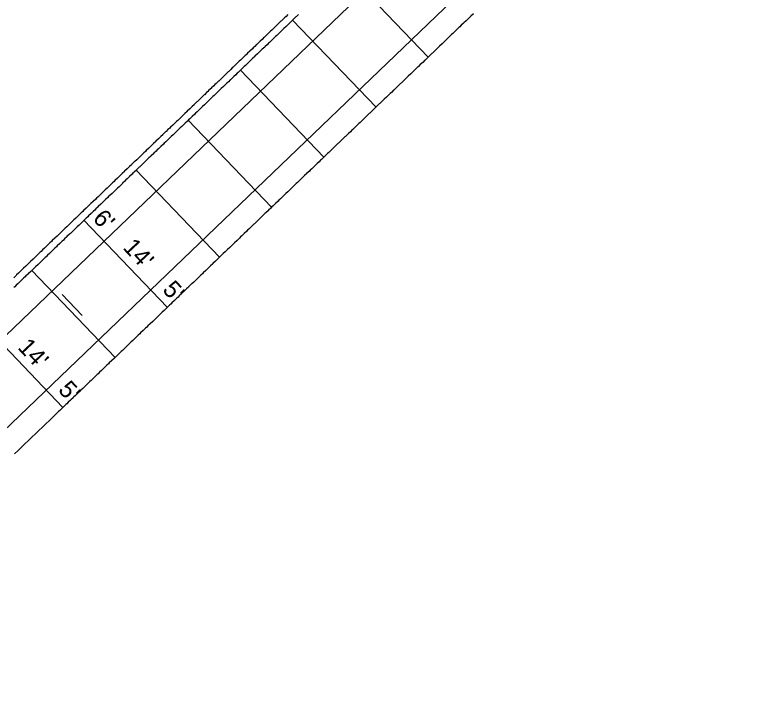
# Model space of a CAD drawing. Extents: x 2145147 to 2158018, y 137519 to 148068.
# Drawn here: x 2150146.3 to 2150298.8, y 143521.5 to 143665.3 of the extents above; entities that cross this region are included whole.
import ezdxf

# ---------------------------------------------------------------- set-up
doc = ezdxf.new("R2010")
doc.units = 0
for name, color, linetype in [('PR_Align_Ramp_B', 7, 'Continuous'), ('PR_Align_Ramp_F', 7, 'Continuous'), ('PR_Dimensions', 7, 'Continuous'), ('PR_Joint_Contraction', 7, 'Continuous'), ('PR_Joint_Long', 7, 'Continuous'), ('PR_Road_Concrete', 7, 'Continuous')]:
    doc.layers.add(name, color=color, linetype=linetype)

msp = doc.modelspace()

# ---------------------------------------------------------------- linework, layer by layer
at = {"layer": 'PR_Align_Ramp_B'}
msp.add_arc((2151085.75, 143191.05), 848.83, 152.5051, 261.84091, dxfattribs=at)
at = {"layer": 'PR_Align_Ramp_F'}
msp.add_lwpolyline([(2150160.31, 143602.96), (2150156.16, 143607.29)], dxfattribs=at)
at = {"layer": 'PR_Joint_Contraction'}
for p, q in [((2150232.12, 143656.54), (2150214.82, 143674.59)), ((2150221.29, 143646.17), (2150203.99, 143664.22)), ((2150210.46, 143635.79), (2150193.16, 143653.84)), ((2150199.63, 143625.41), (2150182.33, 143643.46)), ((2150188.8, 143615.03), (2150171.5, 143633.08)), ((2150177.97, 143604.65), (2150160.67, 143622.7)), ((2150167.14, 143594.27), (2150149.84, 143612.32)), ((2150156.31, 143583.9), (2150139.01, 143601.94))]:
    msp.add_line(p, q, dxfattribs=at)
at = {"layer": 'PR_Joint_Long'}
for points in [[(2150341.04, 143787.25), (2149920.61, 143384.33)], [(2150350.73, 143777.14), (2149930.29, 143374.23)]]:
    msp.add_lwpolyline(points, dxfattribs=at)
at = {"layer": 'PR_Road_Concrete'}
for points in [[(2150203.01, 143665.36), (2150202.64, 143665), (2150202.29, 143664.66), (2150202.14, 143664.52), (2150201.64, 143664.05), (2150201.56, 143663.97), (2150201.14, 143663.57), (2150200.84, 143663.28), (2150200.64, 143663.09), (2150200.14, 143662.61), (2150200.12, 143662.59), (2150199.64, 143662.13), (2150199.4, 143661.9), (2150199.14, 143661.65), (2150198.68, 143661.2), (2150198.64, 143661.17), (2150198.14, 143660.69), (2150197.95, 143660.51), (2150197.63, 143660.21), (2150197.23, 143659.82), (2150197.13, 143659.73), (2150196.63, 143659.25), (2150196.51, 143659.13), (2150196.13, 143658.77), (2150195.79, 143658.44), (2150195.63, 143658.29), (2150195.13, 143657.81), (2150195.07, 143657.75), (2150194.63, 143657.33), (2150194.34, 143657.05), (2150194.13, 143656.85), (2150193.63, 143656.37), (2150193.62, 143656.36), (2150193.13, 143655.89), (2150192.9, 143655.67), (2150192.63, 143655.41), (2150192.18, 143654.98), (2150192.13, 143654.93), (2150191.63, 143654.45), (2150191.46, 143654.29), (2150191.13, 143653.97), (2150190.73, 143653.59), (2150190.63, 143653.49), (2150190.13, 143653.01), (2150190.01, 143652.9), (2150189.63, 143652.53), (2150189.29, 143652.21), (2150189.13, 143652.05), (2150188.63, 143651.57), (2150188.57, 143651.52), (2150188.13, 143651.09), (2150187.85, 143650.83), (2150187.62, 143650.61), (2150187.12, 143650.14), (2150187.12, 143650.13), (2150186.62, 143649.66), (2150186.4, 143649.44), (2150186.12, 143649.18), (2150185.68, 143648.75), (2150185.62, 143648.7), (2150185.12, 143648.22), (2150184.96, 143648.06), (2150184.62, 143647.74), (2150184.24, 143647.37), (2150184.12, 143647.26), (2150183.62, 143646.78), (2150183.51, 143646.67), (2150183.12, 143646.3), (2150182.79, 143645.98), (2150182.62, 143645.82), (2150182.12, 143645.34), (2150182.07, 143645.29), (2150181.62, 143644.86), (2150181.35, 143644.6), (2150181.12, 143644.38), (2150180.63, 143643.91), (2150180.62, 143643.9), (2150180.12, 143643.42), (2150179.9, 143643.22), (2150179.62, 143642.94), (2150179.18, 143642.52), (2150179.12, 143642.46), (2150178.62, 143641.98), (2150178.46, 143641.83), (2150178.11, 143641.5), (2150177.74, 143641.14), (2150177.61, 143641.02), (2150177.11, 143640.54), (2150177.02, 143640.45), (2150176.61, 143640.06), (2150176.29, 143639.76), (2150176.11, 143639.58), (2150175.61, 143639.1), (2150175.57, 143639.06), (2150175.11, 143638.62), (2150174.85, 143638.37), (2150174.61, 143638.14), (2150174.13, 143637.68), (2150174.11, 143637.66), (2150173.61, 143637.18), (2150173.41, 143636.99), (2150173.11, 143636.7), (2150172.68, 143636.3), (2150172.61, 143636.23), (2150172.11, 143635.75), (2150171.96, 143635.6), (2150171.61, 143635.27), (2150171.24, 143634.91), (2150171.11, 143634.79), (2150170.61, 143634.31), (2150170.52, 143634.22), (2150170.11, 143633.83), (2150169.8, 143633.53), (2150169.61, 143633.35), (2150169.11, 143632.87), (2150169.07, 143632.84), (2150168.61, 143632.39), (2150168.35, 143632.14), (2150168.1, 143631.91), (2150167.63, 143631.45), (2150167.6, 143631.43), (2150167.1, 143630.95), (2150166.91, 143630.76), (2150166.6, 143630.47), (2150166.19, 143630.07), (2150166.1, 143629.99), (2150165.6, 143629.51), (2150165.46, 143629.38), (2150165.1, 143629.03), (2150164.74, 143628.69), (2150164.6, 143628.55), (2150164.1, 143628.07), (2150164.02, 143627.99), (2150163.6, 143627.59), (2150163.3, 143627.3), (2150163.1, 143627.11), (2150162.6, 143626.63), (2150162.58, 143626.61), (2150162.1, 143626.15), (2150161.85, 143625.92), (2150161.6, 143625.67), (2150161.13, 143625.23), (2150161.1, 143625.19), (2150160.6, 143624.71), (2150160.41, 143624.53), (2150160.1, 143624.23), (2150159.69, 143623.84), (2150159.6, 143623.75), (2150159.1, 143623.27), (2150158.97, 143623.15), (2150158.59, 143622.79), (2150158.24, 143622.46), (2150158.09, 143622.32), (2150157.59, 143621.84), (2150157.52, 143621.77), (2150157.09, 143621.36), (2150156.8, 143621.07), (2150156.59, 143620.88), (2150156.09, 143620.4), (2150156.08, 143620.38), (2150155.59, 143619.92), (2150155.36, 143619.69), (2150155.09, 143619.44), (2150154.63, 143619), (2150154.59, 143618.96), (2150154.09, 143618.48), (2150153.91, 143618.31), (2150153.59, 143618), (2150153.19, 143617.61), (2150153.09, 143617.52), (2150152.59, 143617.04), (2150152.47, 143616.92), (2150152.09, 143616.56), (2150151.75, 143616.23), (2150151.59, 143616.08), (2150151.09, 143615.6), (2150151.02, 143615.54), (2150150.59, 143615.12), (2150150.3, 143614.85), (2150150.09, 143614.64), (2150149.59, 143614.16), (2150149.58, 143614.16), (2150149.09, 143613.68), (2150148.86, 143613.46), (2150148.58, 143613.2), (2150148.14, 143612.77), (2150148.08, 143612.72), (2150147.58, 143612.24), (2150147.41, 143612.08), (2150147.08, 143611.76), (2150146.69, 143611.39), (2150146.58, 143611.28), (2150146.08, 143610.8)], [(2150205.18, 143665.36), (2150204.77, 143664.96), (2150204.68, 143664.88), (2150204.18, 143664.4), (2150204.05, 143664.27), (2150203.68, 143663.92), (2150203.33, 143663.58), (2150203.18, 143663.44), (2150202.68, 143662.96), (2150202.61, 143662.88), (2150202.18, 143662.48), (2150201.88, 143662.19), (2150201.68, 143662), (2150201.18, 143661.52), (2150201.16, 143661.5), (2150200.68, 143661.04), (2150200.44, 143660.81), (2150200.18, 143660.56), (2150199.72, 143660.12), (2150199.68, 143660.08), (2150199.18, 143659.6), (2150199, 143659.43), (2150198.68, 143659.12), (2150198.27, 143658.73), (2150198.18, 143658.64), (2150197.68, 143658.16), (2150197.55, 143658.04), (2150197.18, 143657.68), (2150196.83, 143657.35), (2150196.68, 143657.2), (2150196.17, 143656.72), (2150196.11, 143656.66), (2150195.67, 143656.24), (2150195.39, 143655.97), (2150195.17, 143655.76), (2150194.67, 143655.28), (2150194.66, 143655.27), (2150194.17, 143654.8), (2150193.94, 143654.58), (2150193.67, 143654.32), (2150193.22, 143653.89), (2150193.17, 143653.84), (2150192.67, 143653.36), (2150192.5, 143653.2), (2150192.17, 143652.88), (2150191.78, 143652.51), (2150191.67, 143652.4), (2150191.17, 143651.93), (2150191.05, 143651.81), (2150190.67, 143651.45), (2150190.33, 143651.12), (2150190.17, 143650.97), (2150189.67, 143650.49), (2150189.61, 143650.43), (2150189.17, 143650.01), (2150188.89, 143649.74), (2150188.67, 143649.53), (2150188.17, 143649.05), (2150188.17, 143649.05), (2150187.67, 143648.57), (2150187.44, 143648.35), (2150187.17, 143648.09), (2150186.72, 143647.66), (2150186.67, 143647.61), (2150186.16, 143647.13), (2150186, 143646.97), (2150185.66, 143646.65), (2150185.28, 143646.28), (2150185.16, 143646.17), (2150184.66, 143645.69), (2150184.56, 143645.59), (2150184.16, 143645.21), (2150183.83, 143644.9), (2150183.66, 143644.73), (2150183.16, 143644.25), (2150183.11, 143644.2), (2150182.66, 143643.77), (2150182.39, 143643.51), (2150182.16, 143643.29), (2150181.67, 143642.82), (2150181.66, 143642.81), (2150181.16, 143642.33), (2150180.95, 143642.13), (2150180.66, 143641.85), (2150180.22, 143641.44), (2150180.16, 143641.37), (2150179.66, 143640.89), (2150179.5, 143640.74), (2150179.16, 143640.41), (2150178.78, 143640.05), (2150178.66, 143639.93), (2150178.16, 143639.45), (2150178.06, 143639.36), (2150177.66, 143638.97), (2150177.34, 143638.67), (2150177.16, 143638.49), (2150176.65, 143638.02), (2150176.61, 143637.98), (2150176.15, 143637.54), (2150175.89, 143637.28), (2150175.65, 143637.06), (2150175.17, 143636.59), (2150175.15, 143636.58), (2150174.65, 143636.1), (2150174.45, 143635.9), (2150174.15, 143635.62), (2150173.73, 143635.21), (2150173.65, 143635.14), (2150173.15, 143634.66), (2150173, 143634.52), (2150172.65, 143634.18), (2150172.28, 143633.82), (2150172.15, 143633.7), (2150171.65, 143633.22), (2150171.56, 143633.13), (2150171.15, 143632.74), (2150170.84, 143632.44), (2150170.65, 143632.26), (2150170.15, 143631.78), (2150170.12, 143631.75), (2150169.65, 143631.3), (2150169.39, 143631.06), (2150169.15, 143630.82), (2150168.67, 143630.37), (2150168.65, 143630.34), (2150168.15, 143629.86), (2150167.95, 143629.67), (2150167.65, 143629.38), (2150167.23, 143628.98), (2150167.15, 143628.9), (2150166.64, 143628.42), (2150166.51, 143628.29), (2150166.14, 143627.94), (2150165.78, 143627.6), (2150165.64, 143627.46), (2150165.14, 143626.98), (2150165.06, 143626.91), (2150164.64, 143626.5), (2150164.34, 143626.21), (2150164.14, 143626.02), (2150163.64, 143625.54), (2150163.62, 143625.52), (2150163.14, 143625.06), (2150162.9, 143624.83), (2150162.64, 143624.58), (2150162.17, 143624.14), (2150162.14, 143624.11), (2150161.64, 143623.63), (2150161.45, 143623.45), (2150161.14, 143623.15), (2150160.73, 143622.75), (2150160.64, 143622.67), (2150160.14, 143622.19), (2150160.01, 143622.06), (2150159.64, 143621.71), (2150159.29, 143621.37), (2150159.14, 143621.23), (2150158.64, 143620.75), (2150158.56, 143620.68), (2150158.14, 143620.27), (2150157.84, 143619.99), (2150157.64, 143619.79), (2150157.13, 143619.31), (2150157.12, 143619.29), (2150156.63, 143618.83), (2150156.4, 143618.6), (2150156.13, 143618.35), (2150155.68, 143617.91), (2150155.63, 143617.87), (2150155.13, 143617.39), (2150154.95, 143617.22), (2150154.63, 143616.91), (2150154.23, 143616.53), (2150154.13, 143616.43), (2150153.63, 143615.95), (2150153.51, 143615.84), (2150153.13, 143615.47), (2150152.79, 143615.14), (2150152.63, 143614.99), (2150152.13, 143614.51), (2150152.07, 143614.45), (2150151.63, 143614.03), (2150151.34, 143613.76), (2150151.13, 143613.55), (2150150.63, 143613.07), (2150150.62, 143613.07), (2150150.13, 143612.59), (2150149.9, 143612.38), (2150149.63, 143612.11), (2150149.18, 143611.68), (2150149.13, 143611.63), (2150148.63, 143611.15), (2150148.46, 143610.99), (2150148.13, 143610.67), (2150147.73, 143610.3), (2150147.63, 143610.2), (2150147.12, 143609.72), (2150147.01, 143609.61), (2150146.62, 143609.24), (2150146.29, 143608.92), (2150146.12, 143608.76)], [(2150241.5, 143665.54), (2150241, 143665.06), (2150240.84, 143664.9), (2150240.5, 143664.58), (2150240.12, 143664.21), (2150240, 143664.1), (2150239.5, 143663.62), (2150239.39, 143663.52), (2150239, 143663.14), (2150238.67, 143662.83), (2150238.5, 143662.66), (2150238, 143662.18), (2150237.95, 143662.13), (2150237.49, 143661.7), (2150237.23, 143661.44), (2150236.99, 143661.22), (2150236.51, 143660.75), (2150236.49, 143660.74), (2150235.99, 143660.26), (2150235.78, 143660.06), (2150235.49, 143659.78), (2150235.06, 143659.37), (2150234.99, 143659.3), (2150234.49, 143658.82), (2150234.34, 143658.68), (2150233.99, 143658.34), (2150233.62, 143657.98), (2150233.49, 143657.86), (2150232.99, 143657.38), (2150232.9, 143657.29), (2150232.49, 143656.9), (2150232.17, 143656.6), (2150231.99, 143656.42), (2150231.49, 143655.94), (2150231.45, 143655.91), (2150230.99, 143655.46), (2150230.73, 143655.22), (2150230.49, 143654.98), (2150230.01, 143654.52), (2150229.99, 143654.5), (2150229.49, 143654.02), (2150229.29, 143653.83), (2150228.99, 143653.54), (2150228.56, 143653.14), (2150228.49, 143653.06), (2150227.98, 143652.58), (2150227.84, 143652.45), (2150227.48, 143652.1), (2150227.12, 143651.76), (2150226.98, 143651.63), (2150226.48, 143651.15), (2150226.4, 143651.06), (2150225.98, 143650.67), (2150225.68, 143650.37), (2150225.48, 143650.19), (2150224.98, 143649.71), (2150224.95, 143649.68), (2150224.48, 143649.23), (2150224.23, 143648.99), (2150223.98, 143648.75), (2150223.51, 143648.3), (2150223.48, 143648.27), (2150222.98, 143647.79), (2150222.79, 143647.6), (2150222.48, 143647.31), (2150222.07, 143646.91), (2150221.98, 143646.83), (2150221.48, 143646.35), (2150221.34, 143646.22), (2150220.98, 143645.87), (2150220.62, 143645.53), (2150220.48, 143645.39), (2150219.98, 143644.91), (2150219.9, 143644.84), (2150219.48, 143644.43), (2150219.18, 143644.15), (2150218.98, 143643.95), (2150218.48, 143643.47), (2150218.46, 143643.45), (2150217.97, 143642.99), (2150217.73, 143642.76), (2150217.47, 143642.51), (2150217.01, 143642.07), (2150216.97, 143642.03), (2150216.47, 143641.55), (2150216.29, 143641.38), (2150215.97, 143641.07), (2150215.57, 143640.69), (2150215.47, 143640.59), (2150214.97, 143640.11), (2150214.85, 143639.99), (2150214.47, 143639.63), (2150214.12, 143639.3), (2150213.97, 143639.15), (2150213.47, 143638.67), (2150213.4, 143638.61), (2150212.97, 143638.19), (2150212.68, 143637.92), (2150212.47, 143637.72), (2150211.97, 143637.24), (2150211.96, 143637.23), (2150211.47, 143636.76), (2150211.24, 143636.53), (2150210.97, 143636.28), (2150210.52, 143635.84), (2150210.47, 143635.8), (2150209.97, 143635.32), (2150209.79, 143635.15), (2150209.47, 143634.84), (2150209.07, 143634.46), (2150208.97, 143634.36), (2150208.46, 143633.88), (2150208.35, 143633.77), (2150207.96, 143633.4), (2150207.63, 143633.07), (2150207.46, 143632.92), (2150206.96, 143632.44), (2150206.91, 143632.38), (2150206.46, 143631.96), (2150206.18, 143631.69), (2150205.96, 143631.48), (2150205.46, 143631), (2150205.46, 143631), (2150204.96, 143630.52), (2150204.74, 143630.31), (2150204.46, 143630.04), (2150204.02, 143629.62), (2150203.96, 143629.56), (2150203.46, 143629.08), (2150203.3, 143628.92), (2150202.96, 143628.6), (2150202.57, 143628.23), (2150202.46, 143628.12), (2150201.96, 143627.64), (2150201.85, 143627.54), (2150201.46, 143627.16), (2150201.13, 143626.85), (2150200.96, 143626.68), (2150200.46, 143626.2), (2150200.41, 143626.16), (2150199.96, 143625.72), (2150199.69, 143625.46), (2150199.46, 143625.24), (2150198.96, 143624.77), (2150198.96, 143624.76), (2150198.45, 143624.28), (2150198.24, 143624.08), (2150197.95, 143623.81), (2150197.52, 143623.39), (2150197.45, 143623.33), (2150196.95, 143622.85), (2150196.8, 143622.7), (2150196.45, 143622.37), (2150196.08, 143622), (2150195.95, 143621.89), (2150195.45, 143621.41), (2150195.35, 143621.31), (2150194.95, 143620.93), (2150194.63, 143620.62), (2150194.45, 143620.45), (2150193.95, 143619.97), (2150193.91, 143619.93), (2150193.45, 143619.49), (2150193.19, 143619.24), (2150192.95, 143619.01), (2150192.47, 143618.54), (2150192.45, 143618.53), (2150191.95, 143618.05), (2150191.74, 143617.85), (2150191.45, 143617.57), (2150191.02, 143617.16), (2150190.95, 143617.09), (2150190.45, 143616.61), (2150190.3, 143616.47), (2150189.95, 143616.13), (2150189.58, 143615.78), (2150189.45, 143615.65), (2150188.94, 143615.17), (2150188.86, 143615.09), (2150188.44, 143614.69), (2150188.13, 143614.39), (2150187.94, 143614.21), (2150187.44, 143613.73), (2150187.41, 143613.7), (2150186.94, 143613.25), (2150186.69, 143613.01), (2150186.44, 143612.77), (2150185.97, 143612.32), (2150185.94, 143612.29), (2150185.44, 143611.81), (2150185.25, 143611.63), (2150184.94, 143611.33), (2150184.52, 143610.93), (2150184.44, 143610.85), (2150183.94, 143610.37), (2150183.8, 143610.24), (2150183.44, 143609.9), (2150183.08, 143609.55), (2150182.94, 143609.42), (2150182.44, 143608.94), (2150182.36, 143608.86), (2150181.94, 143608.46), (2150181.64, 143608.17), (2150181.44, 143607.98), (2150180.94, 143607.5), (2150180.91, 143607.47), (2150180.44, 143607.02), (2150180.19, 143606.78), (2150179.94, 143606.54), (2150179.47, 143606.09), (2150179.44, 143606.06), (2150178.93, 143605.58), (2150178.75, 143605.4), (2150178.43, 143605.1), (2150178.03, 143604.71), (2150177.93, 143604.62), (2150177.43, 143604.14), (2150177.3, 143604.01), (2150176.93, 143603.66), (2150176.58, 143603.32), (2150176.43, 143603.18), (2150175.93, 143602.7), (2150175.86, 143602.63), (2150175.43, 143602.22), (2150175.14, 143601.94), (2150174.93, 143601.74), (2150174.43, 143601.26), (2150174.42, 143601.25), (2150173.93, 143600.78), (2150173.69, 143600.56), (2150173.43, 143600.3), (2150172.97, 143599.86), (2150172.93, 143599.82), (2150172.43, 143599.34), (2150172.25, 143599.17), (2150171.93, 143598.86), (2150171.53, 143598.48), (2150171.43, 143598.38), (2150170.93, 143597.9), (2150170.81, 143597.79), (2150170.43, 143597.42), (2150170.08, 143597.1), (2150169.93, 143596.94), (2150169.42, 143596.46), (2150169.36, 143596.4), (2150168.92, 143595.99), (2150168.64, 143595.71), (2150168.42, 143595.51), (2150167.92, 143595.03), (2150167.92, 143595.02), (2150167.42, 143594.55), (2150167.2, 143594.33), (2150166.92, 143594.07), (2150166.47, 143593.64), (2150166.42, 143593.59), (2150165.92, 143593.11), (2150165.75, 143592.94), (2150165.42, 143592.63), (2150165.03, 143592.25), (2150164.92, 143592.15), (2150164.42, 143591.67), (2150164.31, 143591.56), (2150163.92, 143591.19), (2150163.59, 143590.87), (2150163.42, 143590.71), (2150162.92, 143590.23), (2150162.86, 143590.18), (2150162.42, 143589.75), (2150162.14, 143589.49), (2150161.92, 143589.27), (2150161.42, 143588.79), (2150161.42, 143588.79), (2150160.92, 143588.31), (2150160.7, 143588.1), (2150160.42, 143587.83), (2150159.98, 143587.41), (2150159.92, 143587.35), (2150159.41, 143586.87), (2150159.25, 143586.72), (2150158.91, 143586.39), (2150158.53, 143586.03), (2150158.41, 143585.91), (2150157.91, 143585.43), (2150157.81, 143585.33), (2150157.41, 143584.95), (2150157.09, 143584.64), (2150156.91, 143584.47), (2150156.41, 143583.99), (2150156.37, 143583.95), (2150155.91, 143583.51), (2150155.64, 143583.26), (2150155.41, 143583.03), (2150154.92, 143582.57), (2150154.2, 143581.87), (2150153.48, 143581.18), (2150152.76, 143580.49), (2150152.03, 143579.8), (2150151.31, 143579.11), (2150150.59, 143578.41), (2150149.87, 143577.72), (2150149.15, 143577.03), (2150148.42, 143576.34), (2150147.7, 143575.65), (2150146.98, 143574.96), (2150146.26, 143574.26)]]:
    msp.add_lwpolyline(points, dxfattribs=at)

# ---------------------------------------------------------------- texts
at = {"layer": 'PR_Dimensions'}
for s, p in [("6'", (2150162.32, 143622.91)), ("14'", (2150168.58, 143616.91)), ("5'", (2150176.8, 143608.14)), ("14'", (2150146.75, 143596.2)), ("5'", (2150155.14, 143587.38))]:
    msp.add_text(s, height=3.6, rotation=313.0172, dxfattribs=at).set_placement(p)

doc.saveas('drawing.dxf')
